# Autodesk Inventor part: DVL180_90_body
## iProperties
Created: 2009-09
Part Number: DVL180_90_body
Document SubType Name: Modeling
Designer: TB
Mass: 5964.43 g
Surface Area: 5492.17 cm^2
Volume: 5964.43 cm^3
Density: 1 g/cm^3
Author: TB
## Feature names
1. Kropp [Revolution]
2. Chamfer
3. Extrusion2
4. Hole1
5. Revolution2
6. Hole2
7. Fillet1
